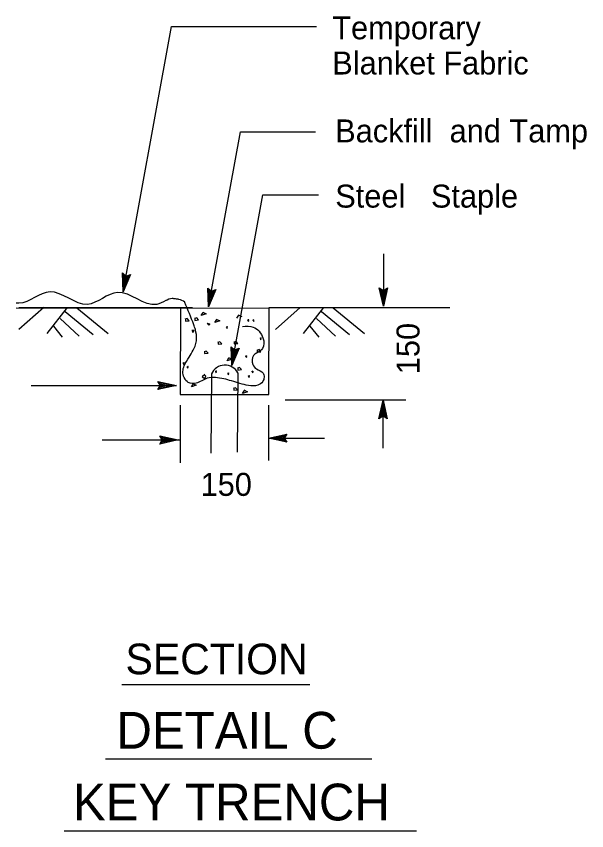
# Model space of a CAD drawing. Extents: x 6712486 to 6713732, y 1869200 to 1869925.
# Drawn here: x 6713035.3 to 6713190.3, y 1869672.2 to 1869893.5 of the extents above; entities that cross this region are included whole.
import ezdxf

# ---------------------------------------------------------------- set-up
doc = ezdxf.new("R2010")
doc.units = 0
for name, color, linetype in [('56 Stg 3 Anno', 7, 'Continuous'), ('57 Undefined', 7, 'Continuous'), ('60 Nongeo Data', 7, 'Continuous'), ('63 Undefined', 7, 'Continuous')]:
    doc.layers.add(name, color=color, linetype=linetype)

msp = doc.modelspace()

# ---------------------------------------------------------------- linework, layer by layer
at = {"layer": '56 Stg 3 Anno'}
for p, q in [((6713064.35, 1869818.65), (6713064.16, 1869823.76)), ((6713064.16, 1869823.76), (6713064.16, 1869823.76)), ((6713064.16, 1869823.76), (6713065.13, 1869822.91)), ((6713066.34, 1869823.36), (6713064.35, 1869818.65)), ((6713064.55, 1869819.79), (6713064.42, 1869823.52)), ((6713064.76, 1869820.91), (6713064.67, 1869823.32)), ((6713065.13, 1869822.91), (6713066.34, 1869823.36)), ((6713066.34, 1869823.36), (6713066.34, 1869823.36)), ((6713066.02, 1869823.24), (6713064.55, 1869819.78)), ((6713065.69, 1869823.1), (6713064.76, 1869820.91)), ((6713064.97, 1869822.04), (6713064.93, 1869823.07)), ((6713065.38, 1869823.01), (6713064.97, 1869822.04)), ((6713087.55, 1869814.54), (6713087.36, 1869819.65)), ((6713087.36, 1869819.65), (6713087.36, 1869819.65)), ((6713087.36, 1869819.65), (6713088.33, 1869818.79)), ((6713089.55, 1869819.25), (6713087.55, 1869814.54)), ((6713087.75, 1869815.67), (6713087.62, 1869819.4)), ((6713089.22, 1869819.12), (6713087.76, 1869815.67)), ((6713087.96, 1869816.8), (6713087.88, 1869819.21)), ((6713088.89, 1869818.99), (6713087.96, 1869816.8)), ((6713088.17, 1869817.93), (6713088.13, 1869818.96)), ((6713088.58, 1869818.89), (6713088.17, 1869817.93)), ((6713088.33, 1869818.79), (6713089.55, 1869819.25)), ((6713089.55, 1869819.25), (6713089.55, 1869819.25)), ((6713135.04, 1869814.71), (6713133.93, 1869819.71)), ((6713133.93, 1869819.71), (6713133.93, 1869819.71)), ((6713133.93, 1869819.71), (6713135.04, 1869819.04)), ((6713135.04, 1869815.87), (6713134.23, 1869819.51)), ((6713135.04, 1869817.01), (6713134.52, 1869819.37)), ((6713135.04, 1869818.16), (6713134.82, 1869819.17)), ((6713135.04, 1869819.04), (6713136.16, 1869819.71)), ((6713136.16, 1869819.71), (6713135.04, 1869814.71)), ((6713135.86, 1869819.53), (6713135.04, 1869815.86)), ((6713135.56, 1869819.33), (6713135.04, 1869817.01)), ((6713135.27, 1869819.19), (6713135.04, 1869818.16)), ((6713136.16, 1869819.71), (6713136.16, 1869819.71)), ((6713064.35, 1869818.65), (6713064.35, 1869818.65)), ((6713087.55, 1869814.54), (6713087.55, 1869814.54)), ((6713135.04, 1869814.71), (6713135.04, 1869814.71)), ((6713093.82, 1869798.59), (6713093.64, 1869803.71)), ((6713093.64, 1869803.71), (6713093.64, 1869803.71)), ((6713093.64, 1869803.71), (6713094.61, 1869802.85)), ((6713094.03, 1869799.73), (6713093.9, 1869803.46)), ((6713095.82, 1869803.31), (6713093.82, 1869798.59)), ((6713095.5, 1869803.18), (6713094.03, 1869799.72)), ((6713094.24, 1869800.86), (6713094.15, 1869803.26)), ((6713095.17, 1869803.04), (6713094.24, 1869800.86)), ((6713094.45, 1869801.99), (6713094.41, 1869803.02)), ((6713094.86, 1869802.95), (6713094.45, 1869801.99)), ((6713094.61, 1869802.85), (6713095.82, 1869803.31)), ((6713095.82, 1869803.31), (6713095.82, 1869803.31)), ((6713093.82, 1869798.59), (6713093.82, 1869798.59)), ((6713133.83, 1869784.17), (6713134.94, 1869789.17)), ((6713134.13, 1869784.35), (6713134.94, 1869788.02)), ((6713134.94, 1869789.17), (6713134.94, 1869789.17)), ((6713134.94, 1869789.17), (6713136.05, 1869784.17)), ((6713134.95, 1869788.01), (6713135.75, 1869784.37)), ((6713134.42, 1869784.55), (6713134.94, 1869786.87)), ((6713134.71, 1869784.7), (6713134.94, 1869785.72)), ((6713134.94, 1869786.87), (6713135.46, 1869784.52)), ((6713134.94, 1869785.72), (6713135.17, 1869784.71)), ((6713134.94, 1869784.84), (6713133.83, 1869784.17)), ((6713133.83, 1869784.17), (6713133.83, 1869784.17)), ((6713136.05, 1869784.17), (6713134.94, 1869784.84)), ((6713136.05, 1869784.17), (6713136.05, 1869784.17)), ((6713074.92, 1869778.39), (6713074.26, 1869779.51)), ((6713074.26, 1869779.51), (6713074.26, 1869779.51)), ((6713074.26, 1869779.51), (6713079.25, 1869778.39)), ((6713074.44, 1869779.21), (6713078.1, 1869778.39)), ((6713103.78, 1869778.88), (6713108.78, 1869779.99)), ((6713104.94, 1869778.89), (6713108.58, 1869779.69)), ((6713106.08, 1869778.88), (6713108.43, 1869779.4)), ((6713107.23, 1869778.88), (6713108.24, 1869779.1)), ((6713108.78, 1869779.99), (6713108.11, 1869778.88)), ((6713108.78, 1869779.99), (6713108.78, 1869779.99)), ((6713079.25, 1869778.39), (6713074.26, 1869777.28)), ((6713074.26, 1869777.28), (6713074.92, 1869778.39)), ((6713074.26, 1869777.28), (6713074.26, 1869777.28)), ((6713078.09, 1869778.39), (6713074.45, 1869777.58)), ((6713076.95, 1869778.39), (6713074.6, 1869777.87)), ((6713074.63, 1869778.91), (6713076.95, 1869778.39)), ((6713074.78, 1869778.62), (6713075.8, 1869778.39)), ((6713075.8, 1869778.39), (6713074.79, 1869778.17)), ((6713079.25, 1869778.39), (6713079.25, 1869778.39)), ((6713108.78, 1869777.77), (6713103.78, 1869778.88)), ((6713103.78, 1869778.88), (6713103.78, 1869778.88)), ((6713108.6, 1869778.06), (6713104.93, 1869778.88)), ((6713108.4, 1869778.36), (6713106.08, 1869778.88)), ((6713108.25, 1869778.65), (6713107.23, 1869778.88)), ((6713108.11, 1869778.88), (6713108.78, 1869777.77)), ((6713108.78, 1869777.77), (6713108.78, 1869777.77))]:
    msp.add_line(p, q, dxfattribs=at)
at = {"layer": '57 Undefined'}
for p, q in [((6713063.98, 1869711.94), (6713115.06, 1869711.94)), ((6713059.53, 1869691.72), (6713131.87, 1869691.72)), ((6713048.27, 1869672.22), (6713144, 1869672.22))]:
    msp.add_line(p, q, dxfattribs=at)
at = {"layer": '60 Nongeo Data'}
for p, q in [((6713064.35, 1869818.65), (6713077.44, 1869890.7)), ((6713077.44, 1869890.7), (6713116.9, 1869890.7)), ((6713087.55, 1869814.54), (6713096.2, 1869862.12)), ((6713096.2, 1869862.12), (6713116.63, 1869862.12)), ((6713093.82, 1869798.59), (6713102.26, 1869845.02)), ((6713102.26, 1869845.02), (6713117.38, 1869845.02)), ((6713135.06, 1869828.99), (6713135.04, 1869814.71)), ((6713042.75, 1869814.4), (6713036.02, 1869808.42)), ((6713112.43, 1869814.4), (6713105.7, 1869808.42)), ((6713036.02, 1869814.39), (6713083.2, 1869814.39)), ((6713049.13, 1869814.36), (6713043.58, 1869807.3)), ((6713048.58, 1869813.3), (6713056.18, 1869807.04)), ((6713051.71, 1869814.33), (6713060.21, 1869807.33)), ((6713080, 1869814.16), (6713103.96, 1869814.33)), ((6713085.56, 1869812.22), (6713086.05, 1869813.02)), ((6713086.85, 1869812.65), (6713085.56, 1869812.22)), ((6713085.93, 1869813.14), (6713086.85, 1869812.65)), ((6713095.23, 1869811.48), (6713095.73, 1869812.28)), ((6713095.61, 1869812.4), (6713096.53, 1869811.91)), ((6713105.7, 1869814.39), (6713152.88, 1869814.39)), ((6713118.8, 1869814.36), (6713113.26, 1869807.3)), ((6713118.26, 1869813.3), (6713125.86, 1869807.04)), ((6713121.39, 1869814.33), (6713129.89, 1869807.33)), ((6713047.19, 1869811.35), (6713052.38, 1869806.63)), ((6713081.73, 1869811.36), (6713081.12, 1869811.17)), ((6713081.24, 1869811.3), (6713081.24, 1869810.68)), ((6713081.24, 1869810.68), (6713082.23, 1869810.8)), ((6713082.23, 1869810.8), (6713081.73, 1869811.36)), ((6713084.32, 1869811.54), (6713083.71, 1869811.36)), ((6713083.83, 1869811.48), (6713083.83, 1869810.86)), ((6713083.83, 1869810.86), (6713084.82, 1869810.99)), ((6713084.82, 1869810.99), (6713084.32, 1869811.54)), ((6713087.16, 1869810.13), (6713087.47, 1869809.7)), ((6713087.16, 1869810.13), (6713087.84, 1869809.94)), ((6713089.25, 1869810.31), (6713089.75, 1869811.11)), ((6713090.55, 1869810.74), (6713089.25, 1869810.31)), ((6713089.62, 1869811.23), (6713090.55, 1869810.74)), ((6713098.41, 1869811.02), (6713098.07, 1869810.86)), ((6713098.13, 1869810.93), (6713098.38, 1869810.56)), ((6713098.38, 1869810.56), (6713098.44, 1869811.05)), ((6713098.44, 1869811.05), (6713098.38, 1869810.99)), ((6713099.83, 1869811.02), (6713099.49, 1869810.86)), ((6713099.55, 1869810.93), (6713099.8, 1869810.56)), ((6713099.8, 1869810.56), (6713099.86, 1869811.05)), ((6713099.86, 1869811.05), (6713099.8, 1869810.99)), ((6713116.87, 1869811.35), (6713122.06, 1869806.63)), ((6713045.35, 1869809.33), (6713047.78, 1869806.35)), ((6713083.58, 1869808.1), (6713083.03, 1869808.1)), ((6713083.09, 1869808.16), (6713083.27, 1869807.6)), ((6713083.27, 1869807.6), (6713083.58, 1869808.1)), ((6713087.47, 1869809.7), (6713087.9, 1869809.76)), ((6713087.9, 1869809.76), (6713087.84, 1869809.94)), ((6713092.61, 1869809.17), (6713092.28, 1869809.02)), ((6713092.34, 1869809.08), (6713092.58, 1869808.71)), ((6713092.58, 1869808.71), (6713092.65, 1869809.2)), ((6713092.65, 1869809.2), (6713092.58, 1869809.14)), ((6713115.03, 1869809.33), (6713117.46, 1869806.35)), ((6713101.8, 1869806.1), (6713101.46, 1869805.94)), ((6713101.52, 1869806), (6713101.77, 1869805.63)), ((6713101.77, 1869805.63), (6713101.83, 1869806.13)), ((6713101.83, 1869806.13), (6713101.77, 1869806.07)), ((6713090.61, 1869805.08), (6713089.99, 1869804.9)), ((6713090.12, 1869805.02), (6713090.12, 1869804.4)), ((6713090.12, 1869804.4), (6713091.1, 1869804.53)), ((6713091.1, 1869804.53), (6713090.61, 1869805.08)), ((6713094.99, 1869805.14), (6713094.37, 1869804.96)), ((6713094.49, 1869805.08), (6713094.49, 1869804.47)), ((6713094.49, 1869804.47), (6713095.48, 1869804.59)), ((6713095.48, 1869804.59), (6713094.99, 1869805.14)), ((6713086.91, 1869802.56), (6713086.3, 1869802.37)), ((6713086.42, 1869802.5), (6713086.42, 1869801.88)), ((6713086.42, 1869801.88), (6713087.41, 1869802)), ((6713087.41, 1869802), (6713086.91, 1869802.56)), ((6713097.86, 1869801.24), (6713097.52, 1869801.08)), ((6713097.58, 1869801.14), (6713097.82, 1869800.77)), ((6713097.82, 1869800.77), (6713097.89, 1869801.27)), ((6713097.89, 1869801.27), (6713097.82, 1869801.2)), ((6713101.28, 1869802.93), (6713100.66, 1869802.74)), ((6713100.78, 1869802.87), (6713100.78, 1869802.25)), ((6713100.78, 1869802.25), (6713101.77, 1869802.37)), ((6713101.77, 1869802.37), (6713101.28, 1869802.93)), ((6713080.84, 1869799.39), (6713080.5, 1869799.24)), ((6713080.56, 1869799.3), (6713080.81, 1869798.93)), ((6713080.81, 1869798.93), (6713080.87, 1869799.42)), ((6713080.87, 1869799.42), (6713080.81, 1869799.36)), ((6713092.58, 1869799.91), (6713093.08, 1869800.71)), ((6713093.88, 1869800.34), (6713092.58, 1869799.91)), ((6713092.95, 1869800.84), (6713093.88, 1869800.34)), ((6713081.95, 1869798.34), (6713081.61, 1869798.19)), ((6713081.67, 1869798.25), (6713081.92, 1869797.88)), ((6713081.92, 1869797.88), (6713081.98, 1869798.37)), ((6713081.98, 1869798.37), (6713081.92, 1869798.31)), ((6713089.66, 1869797.11), (6713089.32, 1869796.96)), ((6713089.38, 1869797.02), (6713089.62, 1869796.65)), ((6713089.62, 1869796.65), (6713089.69, 1869797.14)), ((6713089.69, 1869797.14), (6713089.62, 1869797.08)), ((6713095.97, 1869798.07), (6713095.36, 1869797.88)), ((6713095.48, 1869798), (6713095.48, 1869797.39)), ((6713095.48, 1869797.39), (6713096.47, 1869797.51)), ((6713096.47, 1869797.51), (6713095.97, 1869798.07)), ((6713099.58, 1869797.05), (6713099.24, 1869796.9)), ((6713099.3, 1869796.96), (6713099.55, 1869796.59)), ((6713099.55, 1869796.59), (6713099.61, 1869797.08)), ((6713099.61, 1869797.08), (6713099.55, 1869797.02)), ((6713086.54, 1869796.22), (6713085.8, 1869795.54)), ((6713085.8, 1869795.54), (6713086.48, 1869795.11)), ((6713086.79, 1869795.73), (6713086.48, 1869796.04)), ((6713086.48, 1869795.11), (6713086.79, 1869795.73)), ((6713088.26, 1869774.83), (6713088.41, 1869796.39)), ((6713092.99, 1869796.56), (6713092.65, 1869796.41)), ((6713092.71, 1869796.47), (6713092.95, 1869796.1)), ((6713092.95, 1869796.1), (6713093.02, 1869796.59)), ((6713093.02, 1869796.59), (6713092.95, 1869796.53)), ((6713095.49, 1869796.64), (6713095.34, 1869775.08)), ((6713098.6, 1869795.82), (6713098.26, 1869795.67)), ((6713098.32, 1869795.73), (6713098.56, 1869795.36)), ((6713098.56, 1869795.36), (6713098.63, 1869795.85)), ((6713098.63, 1869795.85), (6713098.56, 1869795.79)), ((6713039.33, 1869793.2), (6713078.78, 1869793.2)), ((6713082.9, 1869792.84), (6713083.4, 1869793.64)), ((6713084.2, 1869793.27), (6713082.9, 1869792.84)), ((6713083.27, 1869793.76), (6713084.2, 1869793.27)), ((6713094.87, 1869792.59), (6713094.25, 1869792.41)), ((6713094.37, 1869792.53), (6713094.37, 1869791.91)), ((6713095.36, 1869792.04), (6713094.87, 1869792.59)), ((6713094.37, 1869791.91), (6713095.36, 1869792.04)), ((6713096.78, 1869791.05), (6713097.27, 1869791.85)), ((6713098.07, 1869791.48), (6713096.78, 1869791.05)), ((6713097.15, 1869791.97), (6713098.07, 1869791.48)), ((6713079.81, 1869787.85), (6713079.81, 1869772.16)), ((6713108.36, 1869789.28), (6713141.15, 1869789.28)), ((6713134.94, 1869776.18), (6713134.94, 1869789.17)), ((6713103.85, 1869787.84), (6713103.84, 1869772.77)), ((6713058.63, 1869778.46), (6713079.6, 1869778.46)), ((6713103.85, 1869778.88), (6713119.01, 1869778.88))]:
    msp.add_line(p, q, dxfattribs=at)
msp.add_lwpolyline([(6713035.28, 1869814.32), (6713079.89, 1869814.23), (6713079.77, 1869790.71), (6713103.88, 1869790.72), (6713103.98, 1869814.41), (6713153.09, 1869814.41)], dxfattribs=at)
msp.add_arc((6713091.98, 1869794.71), 4.01, 28.8752, 155.8761, dxfattribs=at)
for points in [[(6713075.9, 1869816.24), (6713073.43, 1869815.22), (6713062.82, 1869818.5), (6713054.61, 1869815.22), (6713044.45, 1869818.65), (6713035.94, 1869815.52), (6713035.28, 1869815.53)], [(6713081.11, 1869815.82), (6713079.47, 1869816.59), (6713078.56, 1869816.7), (6713077.65, 1869816.82), (6713075.78, 1869816.17)], [(6713096.75, 1869809.26), (6713099.67, 1869809.04), (6713102.31, 1869806.11), (6713102.19, 1869803.22), (6713100.58, 1869801.99), (6713099.72, 1869801.31), (6713099.6, 1869798.85), (6713100.52, 1869797.68), (6713102.37, 1869796.57), (6713102.62, 1869795.46), (6713102.25, 1869794.23), (6713100.89, 1869793.25), (6713098.36, 1869793.19), (6713093.8, 1869794.42), (6713089.42, 1869795.34), (6713087.14, 1869795.16), (6713085.66, 1869794.48), (6713084.12, 1869793.8), (6713082.03, 1869793.99), (6713080.92, 1869795.34), (6713080.55, 1869797), (6713080.92, 1869798.54), (6713082.27, 1869800.88), (6713083.38, 1869802.79), (6713084, 1869804.2), (6713084.25, 1869805.68), (6713083.96, 1869808.37), (6713083.51, 1869809.71), (6713081.04, 1869815.77)]]:
    msp.add_spline(points, degree=3, dxfattribs=at)
at = {"layer": '63 Undefined'}
for p, q in [((6713073.79, 1869794.31), (6713073.79, 1869794.31)), ((6713078.78, 1869793.2), (6713078.78, 1869793.2)), ((6713073.79, 1869792.09), (6713073.79, 1869792.09))]:
    msp.add_line(p, q, dxfattribs=at)
msp.add_lwpolyline([(6713073.79, 1869794.31), (6713078.78, 1869793.2), (6713073.78, 1869792.09), (6713073.96, 1869792.38), (6713077.62, 1869793.19), (6713073.96, 1869794.02), (6713074.14, 1869793.72), (6713076.48, 1869793.2), (6713074.14, 1869792.68), (6713074.32, 1869792.97), (6713075.33, 1869793.2), (6713074.31, 1869793.42), (6713074.45, 1869793.2), (6713073.78, 1869792.09), (6713074.45, 1869793.2)], close=True, dxfattribs=at)

# ---------------------------------------------------------------- texts
at = {"layer": '57 Undefined'}
for s, height, p in [('SECTION', 8.327, (6713064.96, 1869714.73)), ('DETAIL C', 9.992, (6713062.49, 1869694.51)), ('KEY TRENCH', 9.992, (6713050.69, 1869675.01))]:
    msp.add_text(s, height=height, dxfattribs=at).set_placement(p)
at = {"layer": '60 Nongeo Data'}
for s, height, p in [('Temporary ', 6.245, (6713121.15, 1869887.26)), ('Blanket Fabric', 6.2451, (6713121.15, 1869877.69)), ('Backfill  and Tamp', 6.2451, (6713121.94, 1869859.25)), ('Steel   Staple', 6.2451, (6713121.96, 1869841.52)), ('150 ', 6.245, (6713085.37, 1869763.2))]:
    msp.add_text(s, height=height, dxfattribs=at).set_placement(p)
msp.add_text('150 ', height=6.245, rotation=89.9718, dxfattribs=at).set_placement((6713144.85, 1869796.26))

doc.saveas('drawing.dxf')
